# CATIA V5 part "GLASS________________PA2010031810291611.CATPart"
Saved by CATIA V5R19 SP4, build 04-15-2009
Part number: GLASS________________PA2010031810291611
Bounding box of the stored display mesh (mm): x -17.65 to 17.65, y -19.44 to -18.64, z -5.65 to 5.65
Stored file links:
  E:\CadInnWork\InWork\GLASS________________PA2010031810291611.CATPart
  C:\Documents and Settings\moren\Bureau\3D models\Lampe\CATIA_V5\pocket_lamp.CATProduct
  C:\Documents and Settings\moren\Bureau\3D models\Lampe\CATIA_V5\plastic_housing_bottom.CATPart
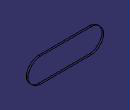
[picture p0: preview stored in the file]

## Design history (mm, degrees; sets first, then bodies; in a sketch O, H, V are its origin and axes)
Parameters
  Update = false
  PDM_version = "A"
  PDM_iteration = 1
  PDM_owner = "moren                    "
  PDM_comment = ""
  PDM_partnumber = "PA002170EA6A57201003181029160011"
Set1
  DatumSurface1: linked copy from another document
  DatumCurve1 to DatumCurve3: linked copy from another document
Body1 (main body)
  Sketch1 on face of DatumSurface1, origin (0, -18.64, 0), H (-1, 0, 0), V (0, 0, 1)
    offset curve E4 from edge of DatumCurve1
    offset line E5 (-12, -5.65) -> (12, -5.65) from edge of DatumCurve2
    offset curve E6 from edge of DatumCurve3
    line L1 (-17.65, 0) -> (17.65, 0)
    horizontal: L1 H
  Pad1: profile Sketch1, direction (0, -1, 0), length 0.8
  Mirror1: of the body so far, about xy-plane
